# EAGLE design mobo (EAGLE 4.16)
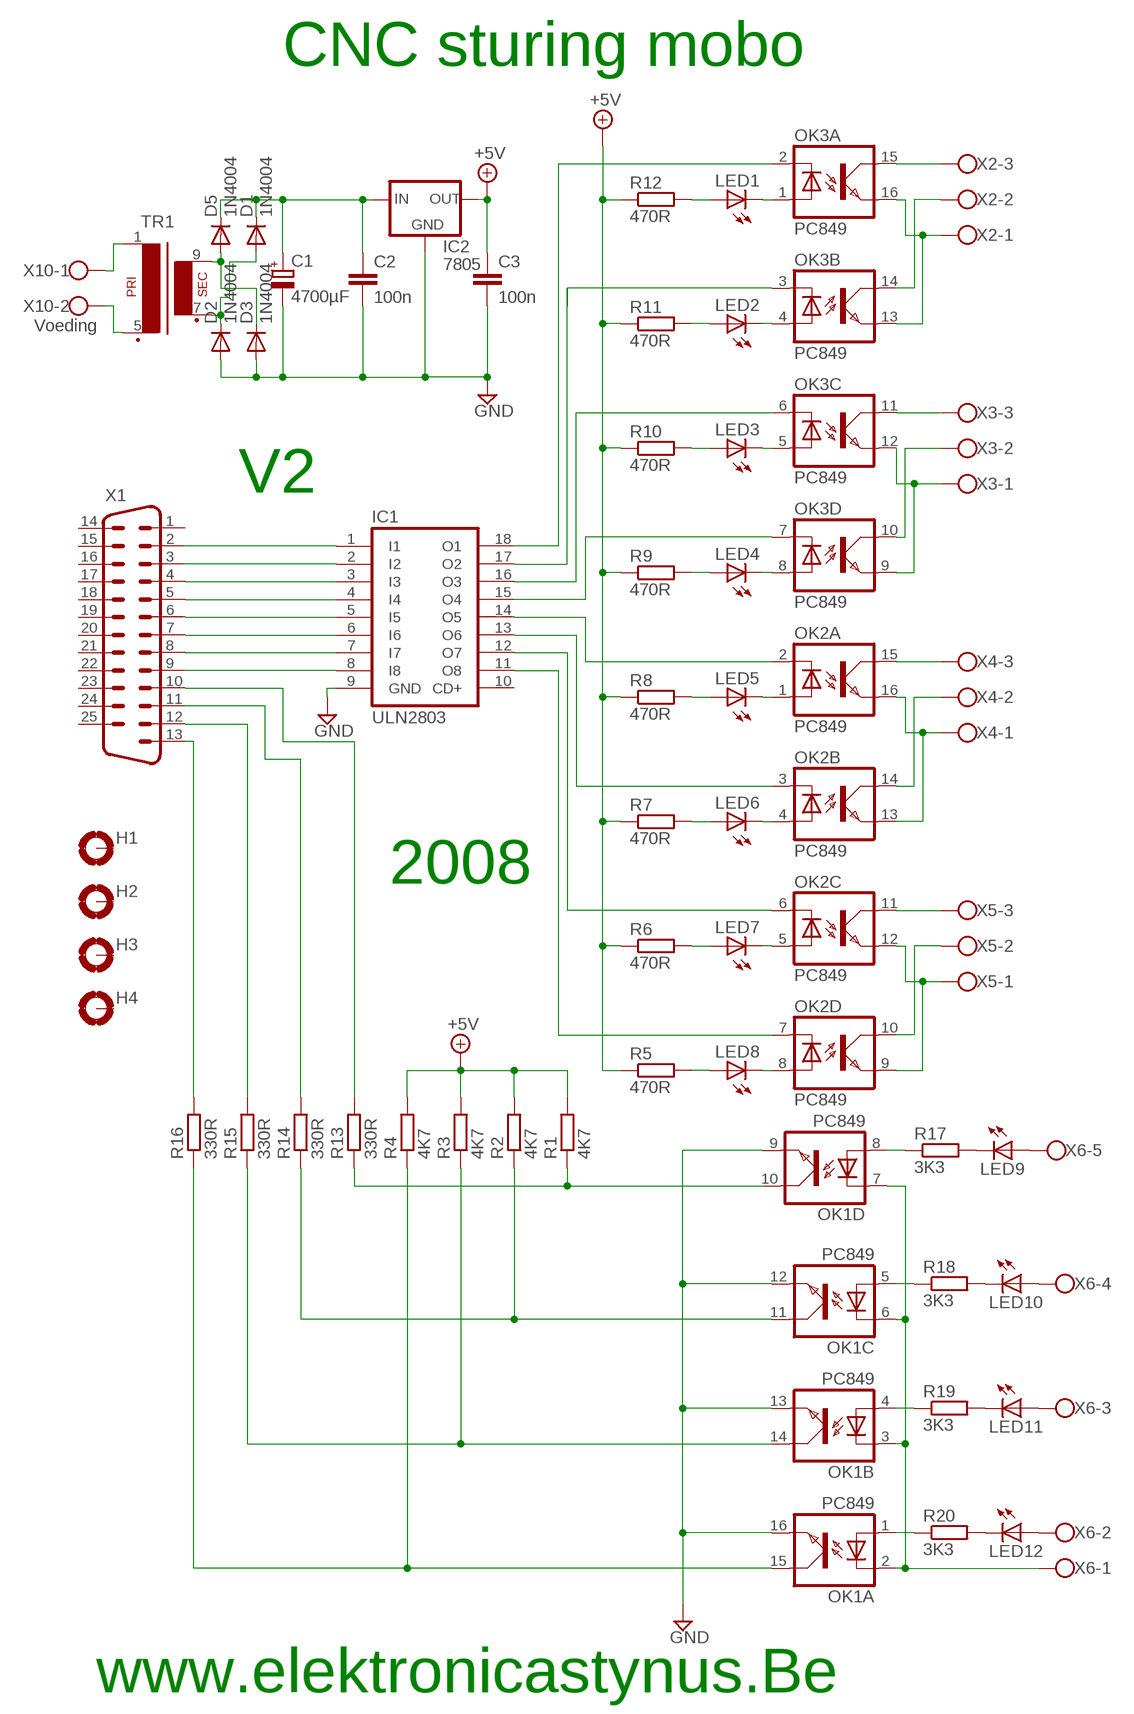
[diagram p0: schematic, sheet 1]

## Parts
C1  4700µF  CPOL-EUE7.5-18  [E7,5-18]
C2  100n  C-EU050-025X075  [C050-025X075]
C3  100n  C-EU050-025X075  [C050-025X075]
D1  1N4004  1N40047.5  [D-7.5]
D2  1N4004  1N40047.5  [D-7.5]
D3  1N4004  1N40047.5  [D-7.5]
D5  1N4004  1N40047.5  [D-7.5]
H1  MOUNT-PAD-ROUND3.0  [3,0-PAD]
H2  MOUNT-PAD-ROUND3.0  [3,0-PAD]
H3  MOUNT-PAD-ROUND3.0  [3,0-PAD]
H4  MOUNT-PAD-ROUND3.0  [3,0-PAD]
IC1  ULN2803  ULN2803A  [DIL18]
IC2  7805  78XXS  [78XXS]
LED1  LED5MM  [LED5MM]
LED2  LED5MM  [LED5MM]
LED3  LED5MM  [LED5MM]
LED4  LED5MM  [LED5MM]
LED5  LED5MM  [LED5MM]
LED6  LED5MM  [LED5MM]
LED7  LED5MM  [LED5MM]
LED8  LED5MM  [LED5MM]
LED9  LED5MM  [LED5MM]
LED10  LED5MM  [LED5MM]
LED11  LED5MM  [LED5MM]
LED12  LED5MM  [LED5MM]
OK1  PC849  [DIL16]
OK2  PC849  [DIL16]
OK3  PC849  [DIL16]
R1  4K7  R-EU_0204/7  [0204/7]
R2  4K7  R-EU_0204/7  [0204/7]
R3  4K7  R-EU_0204/7  [0204/7]
R4  4K7  R-EU_0204/7  [0204/7]
R5  470R  R-EU_0207/12  [0207/12]
R6  470R  R-EU_0207/12  [0207/12]
R7  470R  R-EU_0207/12  [0207/12]
R8  470R  R-EU_0207/12  [0207/12]
R9  470R  R-EU_0207/12  [0207/12]
R10  470R  R-EU_0207/12  [0207/12]
R11  470R  R-EU_0207/12  [0207/12]
R12  470R  R-EU_0207/12  [0207/12]
R13  330R  R-EU_0204/7  [0204/7]
R14  330R  R-EU_0204/7  [0204/7]
R15  330R  R-EU_0204/7  [0204/7]
R16  330R  R-EU_0204/7  [0204/7]
R17  3K3  R-EU_0204/7  [0204/7]
R18  3K3  R-EU_0204/7  [0204/7]
R19  3K3  R-EU_0204/7  [0204/7]
R20  3K3  R-EU_0204/7  [0204/7]
TR1  EI30-1  [EI30-1]
X1  M25H  [M25H]
X2  W237-3E  [W237-3E]
X3  W237-3E  [W237-3E]
X4  W237-3E  [W237-3E]
X5  W237-3E  [W237-3E]
X6  W237-05P  [W237-5P]
X10  Voeding  W237-2N  [W237-2N]

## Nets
+5V: C3.1 IC2.OUT R1.2 R2.2 R3.2 R4.2 R5.1 R6.1 R7.1 R8.1 R9.1 R10.1 R11.1 R12.1
GND: C1.- C2.2 C3.2 D2.A D3.A IC1.9(GND) IC2.GND OK1.9(D:EMI) OK1.12(C:EMI) OK1.13(B:EMI) OK1.16(A:EMI)
N$1: LED1.A R12.2
N$2: LED1.K(C) OK3.1(A:A)
N$3: LED2.K(C) OK3.4(B:A)
N$4: LED2.A R11.2
N$5: LED3.A R10.2
N$6: LED3.K(C) OK3.5(C:A)
N$7: LED4.K(C) OK3.8(D:A)
N$8: LED4.A R9.2
N$9: OK3.15(A:COL) X2.3
N$10: OK2.9(D:EMI) OK2.12(C:EMI) X5.1
N$11: OK3.14(B:COL) X2.2
N$12: OK3.11(C:COL) X3.3
N$13: OK3.9(D:EMI) OK3.12(C:EMI) X3.1
N$14: IC1.18(O1) OK3.2(A:C)
N$15: IC1.17(O2) OK3.3(B:C)
N$16: OK3.10(D:COL) X3.2
N$17: IC1.16(O3) OK3.6(C:C)
N$18: IC1.6(I6) X1.7
N$19: IC1.15(O4) OK3.7(D:C)
N$21: IC1.14(O5) OK2.2(A:C)
N$22: OK1.10(D:COL) R1.1 R13.1
N$23: IC1.13(O6) OK2.3(B:C)
N$24: IC1.12(O7) OK2.6(C:C)
N$25: OK1.11(C:COL) R2.1 R14.1
N$26: OK1.14(B:COL) R3.1 R15.1
N$27: IC1.11(O8) OK2.7(D:C)
N$28: OK1.15(A:COL) R4.1 R16.1
N$29: OK3.13(B:EMI) OK3.16(A:EMI) X2.1
N$30: R15.2 X1.12
N$31: OK2.15(A:COL) X4.3
N$32: R14.2 X1.11
N$33: OK2.13(B:EMI) OK2.16(A:EMI) X4.1
N$34: OK2.14(B:COL) X4.2
N$35: OK2.11(C:COL) X5.3
N$36: OK2.10(D:COL) X5.2
N$37: TR1.5(P2) X10.2
N$38: TR1.1 X10.1
N$39: IC1.1(I1) X1.2
N$40: IC1.2(I2) X1.3
N$41: IC1.3(I3) X1.4
N$42: IC1.4(I4) X1.5
N$43: IC1.5(I5) X1.6
N$44: R13.2 X1.10
N$45: IC1.7(I7) X1.8
N$46: IC1.8(I8) X1.9
N$47: R16.2 X1.13
N$48: OK1.8(D:A) R17.1
N$49: OK1.5(C:A) R18.1
N$50: OK1.4(B:A) R19.1
N$51: OK1.1(A:A) R20.1
N$52: OK1.2(A:C) OK1.3(B:C) OK1.6(C:C) OK1.7(D:C) X6.1
N$53: LED9.K(C) R17.2
N$54: LED9.A X6.5
N$55: LED10.K(C) R18.2
N$56: LED10.A X6.4
N$57: LED5.A R8.2
N$58: LED5.K(C) OK2.1(A:A)
N$59: LED6.A R7.2
N$60: LED6.K(C) OK2.4(B:A)
N$61: LED7.A R6.2
N$62: D3.C D5.A TR1.9(S4)
N$63: D1.A D2.C TR1.7(S3)
N$64: C1.+ C2.1 D1.C D5.C IC2.IN
N$65: LED7.K(C) OK2.5(C:A)
N$66: LED8.K(C) OK2.8(D:A)
N$67: LED8.A R5.2
N$68: LED11.K(C) R19.2
N$69: LED11.A X6.3
N$70: LED12.K(C) R20.2
N$71: LED12.A X6.2
Unconnected: H1.B3,0(MOUNT) H2.B3,0(MOUNT) H3.B3,0(MOUNT) H4.B3,0(MOUNT) IC1.10(CD+) X1.1 X1.14 X1.15 X1.16 X1.17 X1.18 X1.19 X1.20 X1.21 X1.22 X1.23 X1.24 X1.25

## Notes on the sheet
- CNC sturing mobo
- V2
- 2008
- www.elektronicastynus.Be

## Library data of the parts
C1 = rcl:CPOL-EU: POLARIZED CAPACITOR, European symbol
C2 C3 = rcl:C-EU: CAPACITOR, European symbol
D1-D3 D5 = diode:1N4004: DIODE
H1-H4 = holes:MOUNT-PAD-ROUND: MOUNTING PAD, round
IC1 = uln-udn:ULN2803A: DRIVER ARRAY
IC2 = v-reg:78XXS: VOLTAGE REGULATOR
LED1-LED12 = led:LED: LED
OK1-OK3 = optocoupler:PC849: SHARP OPTO COUPLER
R1-R20 = rcl:R-EU_: RESISTOR, European symbol
TR1 = trafo:EI30-1: TRANSFORMER 1 primary winding, 1 secondary winding ERA
X1 = con-subd:M25: HARTING SUB-D
X2-X5 = con-wago-508:W237-3E: WAGO SREW CLAMP
X6 = con-wago-508:W237-05P: WAGO SREW CLAMP
X10 = con-wago-508:W237-2N: WAGO SREW CLAMP

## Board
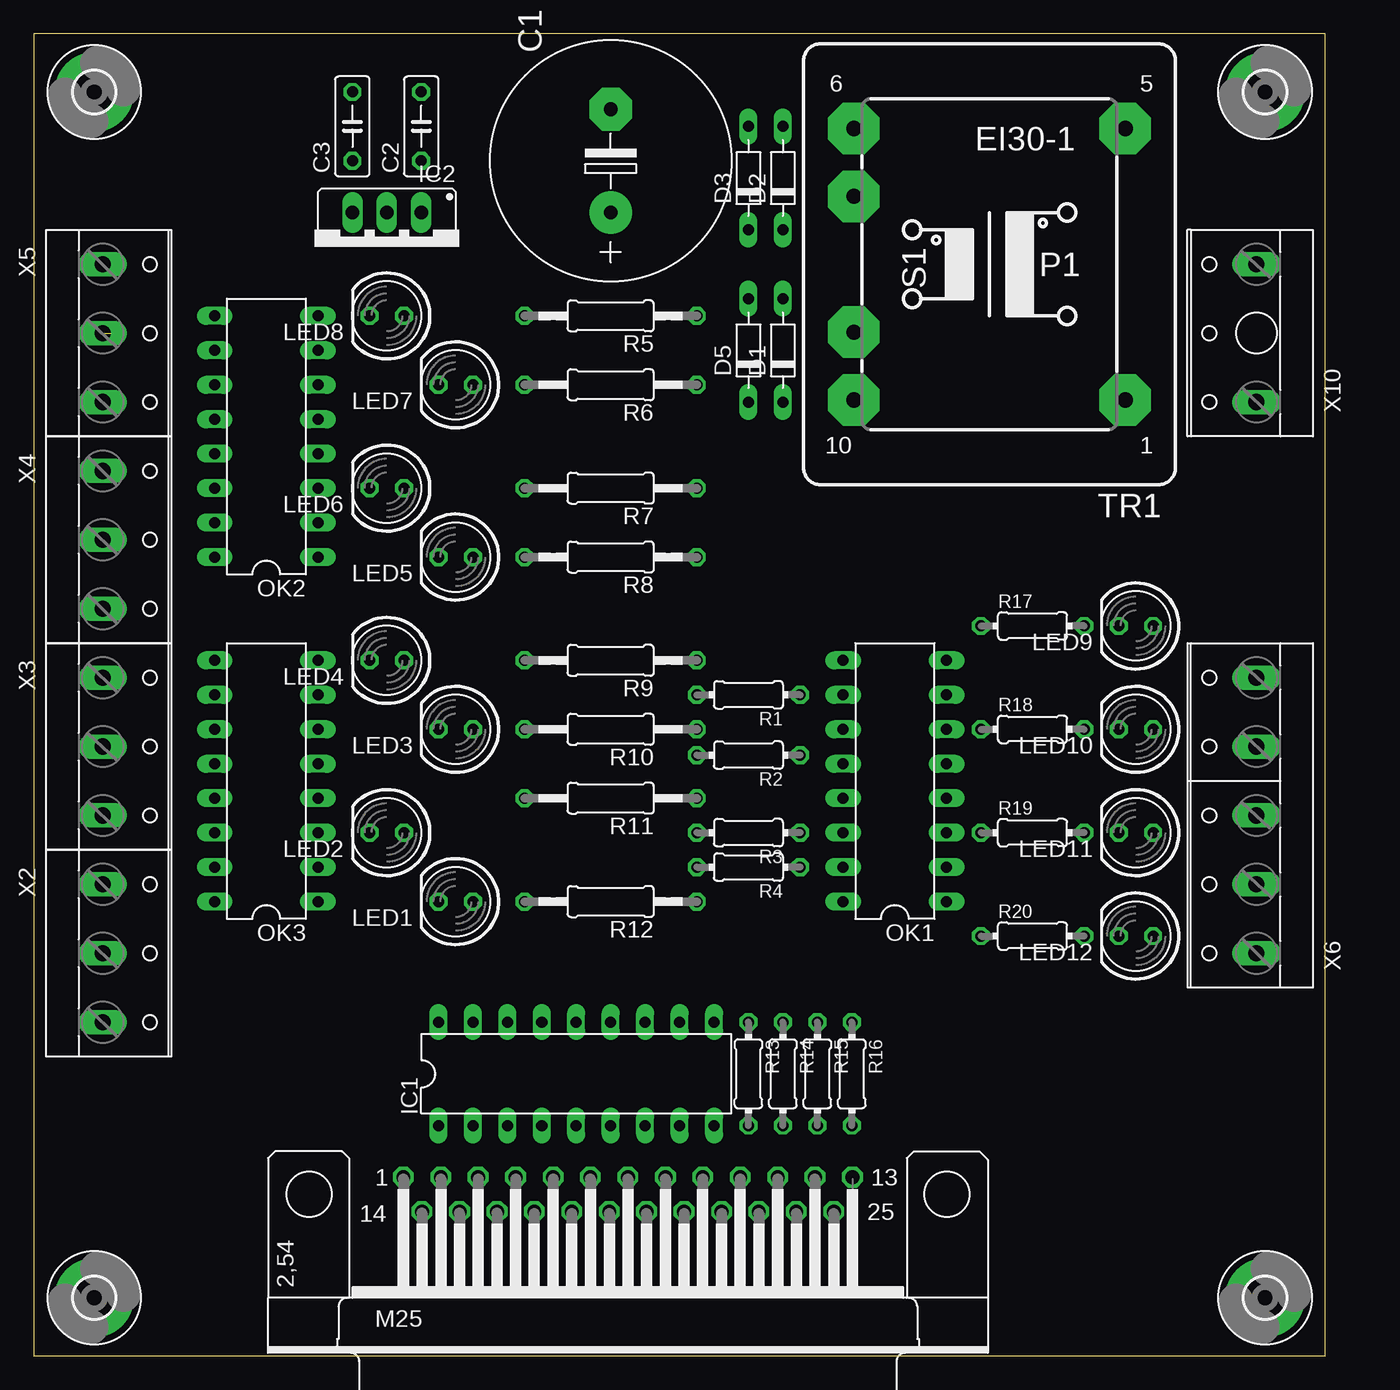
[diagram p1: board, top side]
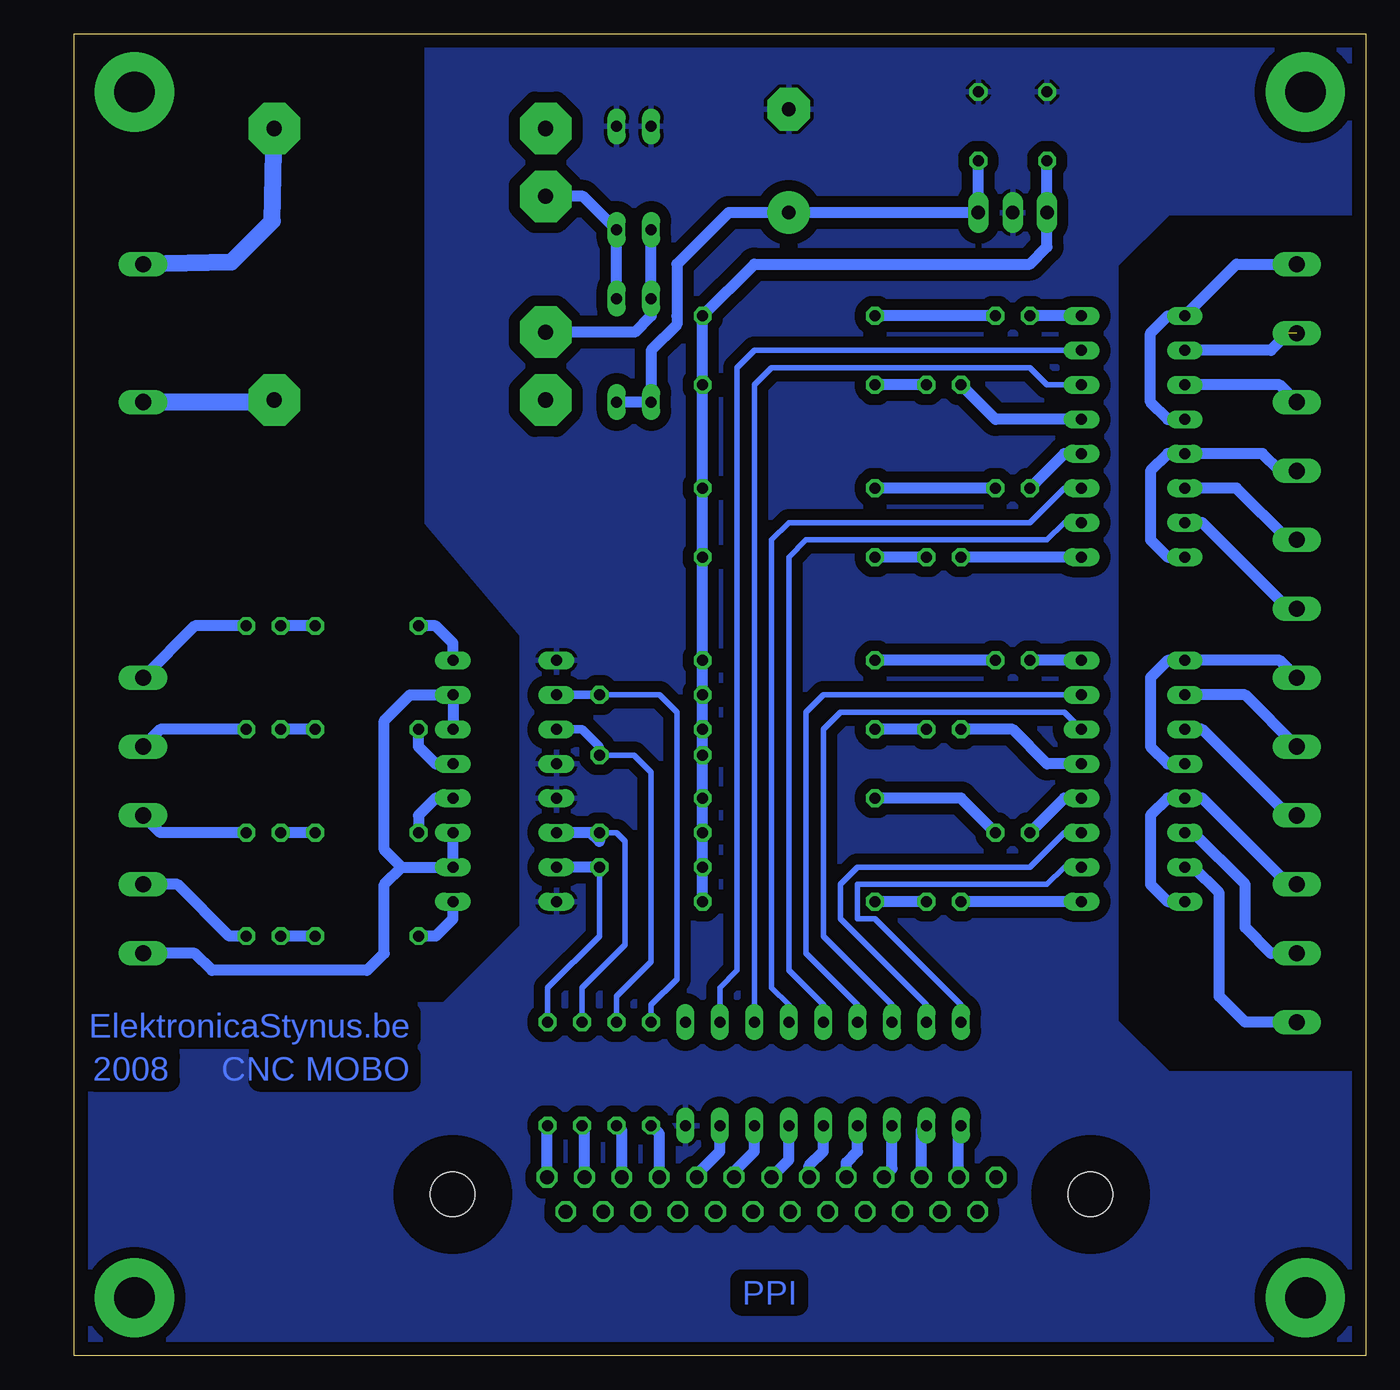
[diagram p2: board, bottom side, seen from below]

Size 95.23 x 97.46 mm. Coordinates in mm from the lower left corner, seen from the top.
Outline: 0,0 95.23,0 95.23,97.46 0,97.46 0,0
Copper layers (1*16): Top 0.035mm / dielectric 1.5mm / Bottom 0.035mm
Design rules "default": minimum track width 10mil, minimum drill 24mil, track to track 8mil, track to pad 8mil, pad to pad 8mil, via to via 8mil, smd to smd 8mil, copper to edge 40mil, drill to drill 8mil, minimum pad ring 10mil, minimum via ring 8mil, stop-mask expansion 4mil, vias tented up to drill 0mil, thermal gap 10mil

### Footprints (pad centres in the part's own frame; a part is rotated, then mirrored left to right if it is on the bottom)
E7,5-18 = drill 1.016 pad 3.15 round: + -3.81,0 | drill 1.016 pad 3.15 octagon: - 3.81,0
C050-025X075 = drill 0.813 octagon: 1 -2.54,0; 2 2.54,0
D-7.5 = drill 0.813 long: A 3.81,0; C -3.81,0
3,0-PAD = drill 3 pad 5.842 round: B3,0 0,0
DIL18 = drill 0.813 long: 1 -10.16,-3.81; 2 -7.62,-3.81; 3 -5.08,-3.81; 4 -2.54,-3.81; 5 0,-3.81; 6 2.54,-3.81; 7 5.08,-3.81; 8 7.62,-3.81; 9 10.16,-3.81; 10 10.16,3.81; 11 7.62,3.81; 12 5.08,3.81; 13 2.54,3.81; 14 0,3.81; 15 -2.54,3.81; 16 -5.08,3.81; 17 -7.62,3.81; 18 -10.16,3.81
78XXS = drill 1.016 long: GND 0,-2.54; IN -2.54,-2.54; OUT 2.54,-2.54
LED5MM = drill 0.813 octagon: A -1.27,0; K 1.27,0
DIL16 = drill 0.813 long: 1 -8.89,-3.81; 2 -6.35,-3.81; 3 -3.81,-3.81; 4 -1.27,-3.81; 5 1.27,-3.81; 6 3.81,-3.81; 7 6.35,-3.81; 8 8.89,-3.81; 9 8.89,3.81; 10 6.35,3.81; 11 3.81,3.81; 12 1.27,3.81; 13 -1.27,3.81; 14 -3.81,3.81; 15 -6.35,3.81; 16 -8.89,3.81
0204/7 = drill 0.813 octagon: 1 -3.81,0; 2 3.81,0
0207/12 = drill 0.813 octagon: 1 -6.35,0; 2 6.35,0
EI30-1 = drill 1.118 pad 3.81 octagon: 1 -10.008,10.008; 5 -10.008,-10.008; 6 10.008,-10.008; 7 10.008,-5.004; 9 10.008,5.004; 10 10.008,10.008
M25H = drill 1.016 octagon: 1 16.561,-1.27; 2 13.792,-1.27; 3 11.049,-1.27; 4 8.28,-1.27; 5 5.512,-1.27; 6 2.769,-1.27; 7 0,-1.27; 8 -2.769,-1.27; 9 -5.512,-1.27; 10 -8.28,-1.27; 11 -11.049,-1.27; 12 -13.792,-1.27; 13 -16.561,-1.27; 14 15.189,1.27; 15 12.421,1.27; 16 9.652,1.27; 17 6.909,1.27; 18 4.14,1.27; 19 1.372,1.27; 20 -1.372,1.27; 21 -4.14,1.27; 22 -6.909,1.27; 23 -9.652,1.27; 24 -12.421,1.27; 25 -15.189,1.27 | hole 3.302: -23.52,0; 23.52,0
W237-3E = drill 1.194 long: 1 -5.08,-0.635; 2 0,-0.635; 3 5.08,-0.635
W237-5P = drill 1.194 long: 1 -10.16,-0.635; 2 -5.08,-0.635; 3 0,-0.635; 4 5.08,-0.635; 5 10.16,-0.635
W237-2N = drill 1.194 long: 1 -5.08,-0.635; 2 5.08,-0.635

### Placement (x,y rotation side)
C1  42.54,88.1 90 top
C2  28.57,90.64 90 top
C3  23.49,90.64 90 top
D1  55.24,74.13 90 top
D2  55.24,86.83 90 top
D3  52.7,86.83 90 top
D5  52.7,74.13 90 top
H1  4.44,93.18 0 top
H2  90.8,93.18 0 top
H3  4.44,4.28 0 top
H4  90.8,4.28 0 top
IC1  40,20.79 0 top
IC2  26.03,81.75 180 top
LED1  31.11,33.49 180 top
LED2  26.03,38.57 180 top
LED3  31.11,46.19 180 top
LED4  26.03,51.27 180 top
LED5  31.11,58.89 180 top
LED6  26.03,63.97 180 top
LED7  31.11,71.59 180 top
LED8  26.03,76.67 180 top
LED9  81.27,53.81 180 top
LED10  81.27,46.19 180 top
LED11  81.27,38.57 180 top
LED12  81.27,30.95 180 top
OK1  63.5,42.38 90 top
OK2  17.14,67.78 90 top
OK3  17.14,42.38 90 top
R1  52.7,48.73 180 top
R2  52.7,44.28 180 top
R3  52.7,38.57 180 top
R4  52.7,36.03 180 top
R5  42.54,76.67 180 top
R6  42.54,71.59 180 top
R7  42.54,63.97 180 top
R8  42.54,58.89 180 top
R9  42.54,51.27 180 top
R10  42.54,46.19 180 top
R11  42.54,41.11 180 top
R12  42.54,33.49 180 top
R13  52.7,20.79 270 top
R14  55.24,20.79 270 top
R15  57.78,20.79 270 top
R16  60.32,20.79 270 top
R17  73.66,53.81 0 top
R18  73.66,46.19 0 top
R19  73.66,38.57 0 top
R20  73.66,30.95 0 top
TR1  70.48,80.48 180 top
X1  43.81,11.9 180 top
X2  5.71,29.68 270 top
X3  5.71,44.92 270 top
X4  5.71,60.16 270 top
X5  5.71,75.4 270 top
X6  89.53,39.84 90 top
X10  89.53,75.4 90 top

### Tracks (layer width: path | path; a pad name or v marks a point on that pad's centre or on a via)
+5V
  Bottom 0.61: R3.2 R4.2
  Bottom 0.813: R12.1 R3.2 | R3.2 R11.1 | R11.1 R2.2 | R2.2 R10.1 | R10.1 R1.2 | R1.2 R9.1 | R9.1 R8.1 | R8.1 R7.1 | R7.1 R6.1 | R6.1 R5.1 | R6.1 R5.1 | R7.1 R6.1 | R8.1 R7.1 | R9.1 R8.1 | R10.1 R1.2 | R1.2 R9.1 | R11.1 R2.2 | R2.2 R10.1 | C3.1 IC2.OUT 23.49,81.75 24.76,80.48 45.08,80.48 R5.1 | R2.2 R1.2 | R1.2 R9.1 | R1.2 R9.1 | R3.2 R11.1
GND
  pour Bottom (isolate 0.813): 0.63,0.47 94.61,0.47 94.61,25.87 67.94,25.87 62.23,31.58 62.23,53.17 69.21,61.43 69.21,96.99 0.63,96.99 0.63,84.29 14.6,84.29 18.41,80.48 18.41,24.6 14.6,20.79 0.63,20.79
N$1
  Bottom 0.813: LED1.A R12.2
N$2
  Bottom 0.813: OK3.1 LED1.K
N$3
  Bottom 0.813: LED2.K 22.22,41.11 OK3.4
N$4
  Bottom 0.813: R11.2 29.84,41.11 LED2.A
N$5
  Bottom 0.813: LED3.A R10.2
N$6
  Bottom 0.813: LED3.K 26.03,46.19 23.49,43.65 OK3.5
N$7
  Bottom 0.813: OK3.8 LED4.K
N$8
  Bottom 0.813: LED4.A R9.2
N$9
  Bottom 0.813: OK3.15 12.7,36.03 10.79,34.12 10.79,26.5 8.89,24.6 X2.3
N$10
  Bottom 0.813: X5.1 9.52,80.48 OK2.9 14.6,76.67 15.87,75.4 15.87,70.32 14.6,69.05 OK2.12
N$11
  Bottom 0.813: OK3.14 12.7,38.57 8.89,34.76 8.89,31.58 6.98,29.68 X2.2
N$12
  Bottom 0.813: X3.3 5.71,39.84 12.06,46.19 OK3.11
N$13
  Bottom 0.813: X3.1 6.34,51.27 OK3.9 14.6,51.27 15.87,50 15.87,44.92 14.6,43.65 OK3.12
N$14
  Bottom 0.406: OK3.2 22.22,36.03 23.49,34.76 37.46,34.76 37.46,32.22 36.19,32.22 29.84,25.87 IC1.18
N$15
  Bottom 0.406: IC1.17 32.38,25.87 38.73,32.22 38.73,34.76 37.46,36.03 24.76,36.03 22.22,38.57 OK3.3
N$16
  Bottom 0.813: OK3.10 8.89,48.73 X3.2
N$17
  Bottom 0.406: IC1.16 34.92,25.87 40,30.95 40,46.19 38.73,47.46 22.22,47.46 OK3.6
N$18
  Bottom 0.813: X1.7 42.54,14.44 IC1.6
N$19
  Bottom 0.406: IC1.15 37.46,25.87 41.27,29.68 41.27,47.46 40,48.73 OK3.7
N$21
  Bottom 0.406: IC1.14 40,25.87 42.54,28.41 42.54,58.89 41.27,60.16 23.49,60.16 22.22,61.43 OK2.2
N$22
  Bottom 0.406: R13.1 52.7,25.87 50.8,27.77 50.8,47.46 52.07,48.73 R1.1
  Bottom 0.61: R1.1 OK1.10
N$23
  Bottom 0.406: IC1.13 42.54,25.87 43.81,27.14 43.81,60.16 42.54,61.43 24.76,61.43 22.22,63.97 OK2.3
N$24
  Bottom 0.406: OK2.6 23.49,71.59 24.76,72.86 43.81,72.86 45.08,71.59 IC1.12
N$25
  Bottom 0.406: R2.1 53.97,44.28 52.7,43.02 52.7,29.04 55.24,26.5 R14.1
  Bottom 0.61: R2.1 56.51,44.92 57.78,46.19 OK1.11 60.32,46.19
N$26
  Bottom 0.406: R15.1 57.78,27.14 54.61,30.31 54.61,37.94 55.24,38.57 R3.1
  Bottom 0.813: R3.1 56.51,37.94 57.15,38.57 OK1.14
N$27
  Bottom 0.406: IC1.11 47.62,27.14 46.35,28.41 46.35,72.86 45.08,74.13 OK2.7
N$28
  Bottom 0.406: OK1.15 R4.1 56.51,30.95 60.32,27.14 R16.1
  Bottom 0.813: R4.1 OK1.15
N$29
  Bottom 0.813: OK3.16 14.6,33.49 15.87,34.76 15.87,39.84 14.6,41.11 OK3.13 12.06,41.11 5.71,34.76 X2.1
N$30
  Bottom 0.813: X1.12 57.6,16.8 R15.2
N$31
  Bottom 0.813: X4.3 5.71,55.08 12.06,61.43 OK2.15
N$32
  Bottom 0.813: X1.11 54.86,16.6 R14.2
N$33
  Bottom 0.813: X4.1 6.34,65.24 7.62,66.51 OK2.13 14.6,66.51 15.87,65.24 15.87,60.16 14.6,58.89 OK2.16
N$34
  Bottom 0.813: OK2.14 9.52,63.97 5.71,60.16 X4.2
N$35
  Bottom 0.813: OK2.11 6.34,71.59 X5.3
N$36  (1 unrouted)
  Bottom 0.813: OK2.10 6.98,74.13 5.71,75.4
N$37
  Bottom 1.27: TR1.5 80.64,83.66 83.66,80.63 X10.2
N$38
  Bottom 1.27: TR1.1 80.64,70.32 X10.1
N$39
  Bottom 0.813: X1.2 30.02,17.44 29.84,17.61 IC1.1
N$40
  Bottom 0.813: X1.3 32.76,16.6 IC1.2
N$41
  Bottom 0.813: X1.4 35.55,13.17 34.92,13.81 IC1.3
N$42
  Bottom 0.813: X1.5 38.3,14.24 37.46,15.08 IC1.4
N$43
  Bottom 0.813: X1.6 41.04,14.03 40,15.08 IC1.5
N$44
  Bottom 0.813: X1.10 52.09,16.37 R13.2
N$45
  Bottom 0.813: X1.8 46.58,13.58 45.08,15.08 IC1.7
N$46
  Bottom 0.813: X1.9 49.32,13.37 47.62,15.08 IC1.8
N$47
  Bottom 0.813: X1.13 60.37,16.93 R16.2
N$48
  Bottom 0.813: R17.1 68.57,53.81 67.3,52.54 OK1.8
N$49
  Bottom 0.813: R18.1 69.84,44.92 68.57,43.65 OK1.5
N$50
  Bottom 0.813: R19.1 69.84,39.84 68.57,41.11 OK1.4
N$51
  Bottom 0.813: R20.1 68.57,30.95 67.3,32.22 OK1.1
N$52
  Bottom 0.813: OK1.6 OK1.7 70.48,48.73 72.38,46.82 72.38,37.3 71.11,36.03 | OK1.3 OK1.2 71.11,36.03 | X6.1 86.35,29.68 85.08,28.41 73.66,28.41 72.38,29.68 72.38,34.76 71.11,36.03
N$53
  Bottom 0.813: R17.2 LED9.K
N$54
  Bottom 0.813: LED9.A 86.35,53.81 X6.5
N$55
  Bottom 0.813: R18.2 LED10.K
N$56
  Bottom 0.813: LED10.A 88.89,46.19 X6.4
N$57
  Bottom 0.813: LED5.A R8.2
N$58
  Bottom 0.813: OK2.1 LED5.K
N$59
  Bottom 0.813: LED6.A R7.2
N$60
  Bottom 0.813: OK2.4 22.22,66.51 LED6.K
N$61
  Bottom 0.813: LED7.A R6.2
N$62
  Bottom 0.813: TR1.9 53.89,75.48 52.7,76.67 D5.A D3.C
N$63
  Bottom 0.813: TR1.7 57.7,85.48 D2.C D1.A
N$64
  Bottom 0.813: C2.1 IC2.IN C1.+ 46.98,84.29 50.8,80.48 50.8,76.67 50.8,76.03 52.7,74.13 D5.C D1.C
N$65
  Bottom 0.813: OK2.5 27.3,69.05 LED7.K
N$66
  Bottom 0.813: OK2.8 LED8.K
N$67
  Bottom 0.813: LED8.A R5.2
N$68
  Bottom 0.813: R19.2 LED11.K
N$69
  Bottom 0.813: LED11.A 88.89,38.57 X6.3
N$70
  Bottom 0.813: R20.2 LED12.K
N$71
  Bottom 0.813: LED12.A 83.81,30.95 87.62,34.76 X6.2

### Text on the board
Bottom: ElektronicaStynus.be | CNC MOBO | 2008 | PPI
